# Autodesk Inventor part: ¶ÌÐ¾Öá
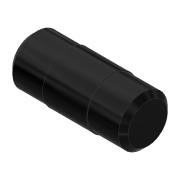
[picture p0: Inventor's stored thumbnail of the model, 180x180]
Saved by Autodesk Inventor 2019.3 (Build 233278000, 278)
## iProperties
Created: 2017-10
Part Number: ¶ÌÐ¾Öá
Material: Ogólny
Document SubType Name: Modeling
Designer: CADENGINEERING4
Density: 1 g/cm^3
Appearance: Gładki — czarny
Author: CADENGINEERING4
Revision Number: ÈÎºÎ
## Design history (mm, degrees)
feature "Ðý×ª1"
node "Bryła1"
